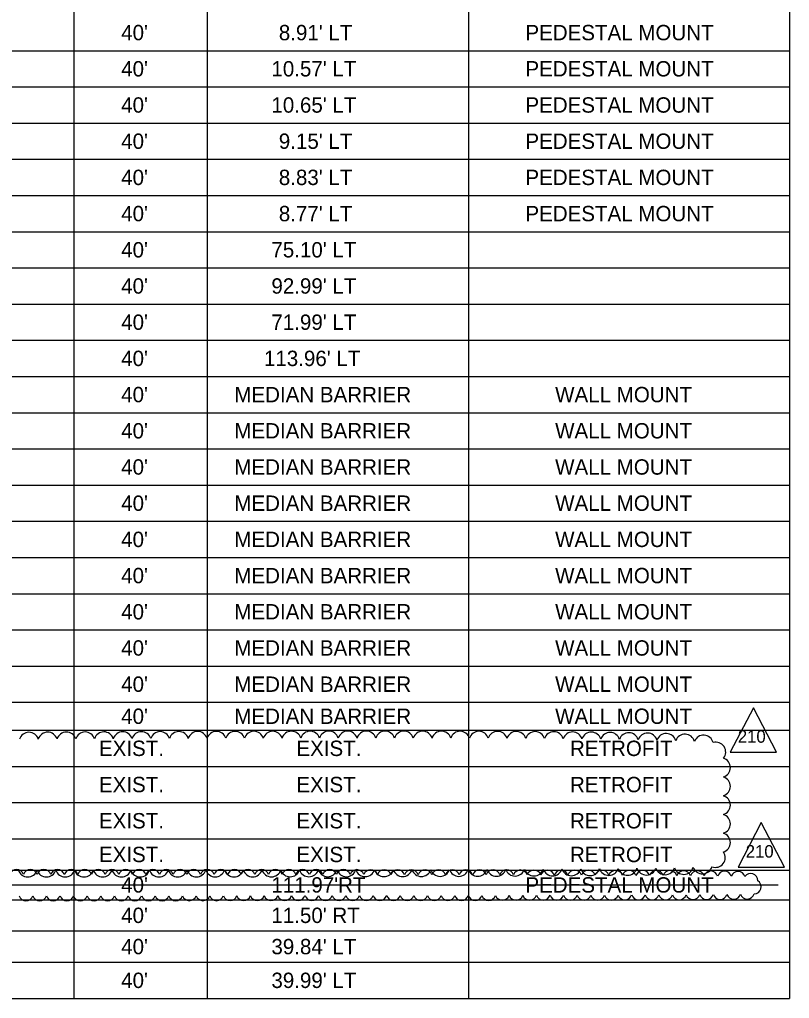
# Model space of a CAD drawing. Extents: x -818.1 to -802.4, y -2221.2 to -2187.7.
# Drawn here: x -813.196 to -809.686, y -2206.269 to -2201.807 of the extents above; entities that cross this region are included whole.
import ezdxf

# ---------------------------------------------------------------- set-up
doc = ezdxf.new("R2010")
doc.units = 0
for name, color, linetype in [('Cloud_dp', 7, 'Continuous'), ('SumBoxBorder_dp', 7, 'Continuous'), ('SumBoxLines_dp', 7, 'Continuous'), ('SumBoxLinesMin_dp', 7, 'Continuous'), ('TextLabel', 7, 'Continuous')]:
    doc.layers.add(name, color=color, linetype=linetype)

msp = doc.modelspace()

# ---------------------------------------------------------------- linework, layer by layer
at = {"layer": 'Cloud_dp'}
msp.add_line((-817.0974, -2205.7517), (-809.7376, -2205.7517), dxfattribs=at)
for points in [[(-809.85, -2204.9439), (-809.9557, -2205.1473), (-809.7444, -2205.1473)], [(-809.8139, -2205.4676), (-809.9195, -2205.6711), (-809.7083, -2205.6711)]]:
    msp.add_lwpolyline(points, close=True, dxfattribs=at)
for centre, radius, start, end in [((-812.2982, -2205.0969), 0.0448, 17.6898, 162.6898), ((-812.2127, -2205.0966), 0.0448, 17.6723, 162.6723), ((-812.1272, -2205.0964), 0.0448, 17.6538, 162.6538), ((-812.0418, -2205.0962), 0.0448, 17.6341, 162.6341), ((-811.9563, -2205.096), 0.0448, 17.6131, 162.6131), ((-811.8708, -2205.0959), 0.0448, 17.5908, 162.5908), ((-811.7854, -2205.0957), 0.0448, 17.5668, 162.5668), ((-811.6999, -2205.0957), 0.0448, 17.5411, 162.5411), ((-811.6144, -2205.0956), 0.0448, 17.5134, 162.5134), ((-811.529, -2205.0956), 0.0448, 17.4834, 162.4834), ((-811.4435, -2205.0957), 0.0448, 17.4509, 162.4509), ((-811.358, -2205.0958), 0.0448, 17.4153, 162.4153), ((-811.2726, -2205.0959), 0.0448, 17.3762, 162.3762), ((-811.1871, -2205.0961), 0.0448, 17.333, 162.333), ((-811.1016, -2205.0964), 0.0448, 17.285, 162.285), ((-811.0162, -2205.0968), 0.0448, 17.231, 162.231), ((-813.1529, -2205.1008), 0.0448, 17.8129, 162.8129), ((-813.0674, -2205.1003), 0.0448, 17.8098, 162.8098), ((-812.982, -2205.0999), 0.0448, 17.8016, 162.8016), ((-812.8965, -2205.0995), 0.0448, 17.7899, 162.7899), ((-812.811, -2205.099), 0.0448, 17.7775, 162.7775), ((-812.7255, -2205.0986), 0.0448, 17.7646, 162.7646), ((-812.6401, -2205.0982), 0.0448, 17.7511, 162.7511), ((-812.5546, -2205.0979), 0.0448, 17.737, 162.737), ((-812.4691, -2205.0975), 0.0448, 17.7221, 162.7221), ((-812.3837, -2205.0972), 0.0448, 17.7064, 162.7064), ((-810.9307, -2205.0972), 0.0448, 17.1699, 162.1699), ((-810.8452, -2205.0978), 0.0448, 17.0999, 162.0999), ((-810.7598, -2205.0984), 0.0448, 17.0185, 162.0185), ((-810.6743, -2205.0992), 0.0448, 16.9224, 161.9224), ((-810.5889, -2205.1002), 0.0448, 16.8064, 161.8064), ((-810.5035, -2205.1013), 0.0448, 16.6627, 161.6627), ((-810.418, -2205.1027), 0.0448, 16.4778, 161.4778), ((-810.3326, -2205.1044), 0.0448, 16.2276, 161.2276), ((-810.2473, -2205.1066), 0.0448, 15.861, 160.861), ((-810.162, -2205.1095), 0.0448, 15.2441, 160.2441), ((-810.077, -2205.1139), 0.0448, 13.804, 158.804), ((-810.021, -2205.1462), 0.0448, 321.1304, 106.1304), ((-809.9996, -2205.2171), 0.0448, 287.5, 72.5), ((-809.9996, -2205.3025), 0.0448, 287.5, 72.5), ((-809.9996, -2205.388), 0.0448, 287.5, 72.5), ((-809.9996, -2205.4735), 0.0448, 287.5, 72.5), ((-809.9996, -2205.559), 0.0448, 287.5, 72.5), ((-810.0231, -2205.627), 0.0448, 249.3736, 34.3736), ((-810.5091, -2205.6637), 0.0448, 198.0389, 343.0389), ((-810.4236, -2205.6629), 0.0448, 198.1252, 343.1252), ((-810.3382, -2205.6618), 0.0448, 198.2415, 343.2415), ((-810.2527, -2205.6606), 0.0448, 198.4108, 343.4108), ((-810.1673, -2205.659), 0.0448, 198.6925, 343.6925), ((-810.082, -2205.6568), 0.0448, 199.3286, 344.3286), ((-813.2089, -2205.7137), 0.0325, 17.4918, 162.4918), ((-813.1586, -2205.6707), 0.0448, 197.4879, 342.4879), ((-813.1468, -2205.7137), 0.0325, 17.4899, 162.4899), ((-813.0732, -2205.6707), 0.0448, 197.496, 342.496), ((-813.0848, -2205.7137), 0.0325, 17.4881, 162.4881), ((-813.0227, -2205.7137), 0.0325, 17.4861, 162.4861), ((-812.9877, -2205.6707), 0.0448, 197.5026, 342.5026), ((-812.9607, -2205.7137), 0.0325, 17.4841, 162.4841), ((-812.9022, -2205.6707), 0.0448, 197.5082, 342.5082), ((-812.8986, -2205.7138), 0.0325, 17.4821, 162.4821), ((-812.8366, -2205.7138), 0.0325, 17.48, 162.48), ((-812.8168, -2205.6707), 0.0448, 197.514, 342.514), ((-812.7745, -2205.7138), 0.0325, 17.4778, 162.4778), ((-812.7313, -2205.6706), 0.0448, 197.5201, 342.5201), ((-812.7124, -2205.7138), 0.0325, 17.4755, 162.4755), ((-812.6458, -2205.6706), 0.0448, 197.5265, 342.5265), ((-812.6504, -2205.7138), 0.0325, 17.4732, 162.4732), ((-812.5883, -2205.7139), 0.0325, 17.4708, 162.4708), ((-812.5603, -2205.6705), 0.0448, 197.5333, 342.5333), ((-812.5263, -2205.7139), 0.0325, 17.4683, 162.4683), ((-812.4749, -2205.6705), 0.0448, 197.5403, 342.5403), ((-812.4642, -2205.7139), 0.0325, 17.4657, 162.4657), ((-812.4021, -2205.714), 0.0325, 17.463, 162.463), ((-812.3894, -2205.6704), 0.0448, 197.5477, 342.5477), ((-812.3401, -2205.714), 0.0325, 17.4602, 162.4602), ((-812.3039, -2205.6704), 0.0448, 197.5556, 342.5556), ((-812.278, -2205.7141), 0.0325, 17.4573, 162.4573), ((-812.2184, -2205.6703), 0.0448, 197.5639, 342.5639), ((-812.216, -2205.7141), 0.0325, 17.4543, 162.4543), ((-812.1539, -2205.7142), 0.0325, 17.4512, 162.4512), ((-812.133, -2205.6702), 0.0448, 197.5726, 342.5726), ((-812.0919, -2205.7142), 0.0325, 17.448, 162.448), ((-812.0475, -2205.67), 0.0448, 197.5819, 342.5819), ((-812.0298, -2205.7143), 0.0325, 17.4446, 162.4446), ((-811.962, -2205.6699), 0.0448, 197.5918, 342.5918), ((-811.9677, -2205.7143), 0.0325, 17.4411, 162.4411), ((-811.9057, -2205.7144), 0.0325, 17.4374, 162.4374), ((-811.8765, -2205.6698), 0.0448, 197.6024, 342.6024), ((-811.8436, -2205.7145), 0.0325, 17.4335, 162.4335), ((-811.7911, -2205.6696), 0.0448, 197.6137, 342.6137), ((-811.7816, -2205.7146), 0.0325, 17.4294, 162.4294), ((-811.7195, -2205.7146), 0.0325, 17.4252, 162.4252), ((-811.7056, -2205.6694), 0.0448, 197.6259, 342.6259), ((-811.6575, -2205.7147), 0.0325, 17.4207, 162.4207), ((-811.6201, -2205.6692), 0.0448, 197.639, 342.639), ((-811.5954, -2205.7148), 0.0325, 17.416, 162.416), ((-811.5347, -2205.669), 0.0448, 197.6531, 342.6531), ((-811.5333, -2205.7149), 0.0325, 17.411, 162.411), ((-811.4713, -2205.715), 0.0325, 17.4057, 162.4057), ((-811.4492, -2205.6688), 0.0448, 197.6685, 342.6685), ((-811.4092, -2205.7151), 0.0325, 17.4002, 162.4002), ((-811.3637, -2205.6685), 0.0448, 197.6853, 342.6853), ((-811.3472, -2205.7152), 0.0325, 17.3942, 162.3942), ((-811.2782, -2205.6682), 0.0448, 197.7038, 342.7038), ((-811.2851, -2205.7153), 0.0325, 17.3879, 162.3879), ((-811.223, -2205.7155), 0.0325, 17.3812, 162.3812), ((-811.1928, -2205.6679), 0.0448, 197.7241, 342.7241), ((-811.161, -2205.7156), 0.0325, 17.374, 162.374), ((-811.1073, -2205.6676), 0.0448, 197.7468, 342.7468), ((-811.0989, -2205.7157), 0.0325, 17.3662, 162.3662), ((-811.0369, -2205.7159), 0.0325, 17.3579, 162.3579), ((-811.0218, -2205.6672), 0.0448, 197.7722, 342.7722), ((-810.9748, -2205.716), 0.0325, 17.3488, 162.3488), ((-810.9364, -2205.6667), 0.0448, 197.801, 342.801), ((-810.9128, -2205.7162), 0.0325, 17.339, 162.339), ((-810.8509, -2205.6663), 0.0448, 197.8339, 342.8339), ((-810.8507, -2205.7164), 0.0325, 17.3282, 162.3282), ((-810.7887, -2205.7166), 0.0325, 17.3164, 162.3164), ((-810.7654, -2205.6657), 0.0448, 197.8722, 342.8722), ((-810.7266, -2205.7168), 0.0325, 17.3033, 162.3033), ((-810.68, -2205.6651), 0.0448, 197.9173, 342.9173), ((-810.6645, -2205.717), 0.0325, 17.2888, 162.2888), ((-810.5945, -2205.6645), 0.0448, 197.9717, 342.9717), ((-810.6025, -2205.7172), 0.0325, 17.2724, 162.2724), ((-810.5404, -2205.7175), 0.0325, 17.2538, 162.2538), ((-810.4784, -2205.7178), 0.0325, 17.2324, 162.2324), ((-810.4163, -2205.7181), 0.0325, 17.2076, 162.2076), ((-810.3543, -2205.7184), 0.0325, 17.1781, 162.1781), ((-810.2922, -2205.7188), 0.0325, 17.1424, 162.1424), ((-810.2302, -2205.7192), 0.0325, 17.098, 162.098), ((-810.1681, -2205.7197), 0.0325, 17.0404, 162.0404), ((-810.1061, -2205.7202), 0.0325, 16.9617, 161.9617), ((-810.044, -2205.7208), 0.0325, 16.8443, 161.8443), ((-809.982, -2205.7217), 0.0325, 16.6401, 161.6401), ((-809.9201, -2205.7229), 0.0325, 16.1079, 161.1079), ((-809.8623, -2205.7327), 0.0325, 359.6037, 144.6037), ((-809.8475, -2205.7602), 0.0325, 271.8825, 56.8825), ((-813.1665, -2205.7914), 0.0325, 197.5069, 342.5069), ((-813.1045, -2205.7914), 0.0325, 197.5084, 342.5084), ((-813.0424, -2205.7914), 0.0325, 197.51, 342.51), ((-812.9803, -2205.7913), 0.0325, 197.5116, 342.5116), ((-812.9183, -2205.7913), 0.0325, 197.5133, 342.5133), ((-812.8562, -2205.7913), 0.0325, 197.515, 342.515), ((-812.7942, -2205.7913), 0.0325, 197.5168, 342.5168), ((-812.7321, -2205.7913), 0.0325, 197.5186, 342.5186), ((-812.6701, -2205.7913), 0.0325, 197.5205, 342.5205), ((-812.608, -2205.7912), 0.0325, 197.5224, 342.5224), ((-812.5459, -2205.7912), 0.0325, 197.5245, 342.5245), ((-812.4839, -2205.7912), 0.0325, 197.5265, 342.5265), ((-812.4218, -2205.7911), 0.0325, 197.5287, 342.5287), ((-812.3598, -2205.7911), 0.0325, 197.531, 342.531), ((-812.2977, -2205.7911), 0.0325, 197.5333, 342.5333), ((-812.2356, -2205.791), 0.0325, 197.5357, 342.5357), ((-812.1736, -2205.791), 0.0325, 197.5382, 342.5382), ((-812.1115, -2205.791), 0.0325, 197.5408, 342.5408), ((-812.0495, -2205.7909), 0.0325, 197.5435, 342.5435), ((-811.9874, -2205.7909), 0.0325, 197.5464, 342.5464), ((-811.9254, -2205.7908), 0.0325, 197.5493, 342.5493), ((-811.8633, -2205.7908), 0.0325, 197.5524, 342.5524), ((-811.8012, -2205.7907), 0.0325, 197.5557, 342.5557), ((-811.7392, -2205.7906), 0.0325, 197.5591, 342.5591), ((-811.6771, -2205.7906), 0.0325, 197.5627, 342.5627), ((-811.6151, -2205.7905), 0.0325, 197.5664, 342.5664), ((-811.553, -2205.7904), 0.0325, 197.5704, 342.5704), ((-811.491, -2205.7903), 0.0325, 197.5745, 342.5745), ((-811.4289, -2205.7903), 0.0325, 197.579, 342.579), ((-811.3668, -2205.7902), 0.0325, 197.5836, 342.5836), ((-811.3048, -2205.7901), 0.0325, 197.5886, 342.5886), ((-811.2427, -2205.79), 0.0325, 197.5939, 342.5939), ((-811.1807, -2205.7899), 0.0325, 197.5996, 342.5996), ((-811.1186, -2205.7898), 0.0325, 197.6056, 342.6056), ((-811.0565, -2205.7897), 0.0325, 197.6121, 342.6121), ((-810.9945, -2205.7895), 0.0325, 197.6192, 342.6192), ((-810.9324, -2205.7894), 0.0325, 197.6268, 342.6268), ((-810.8704, -2205.7893), 0.0325, 197.6351, 342.6351), ((-810.8083, -2205.7891), 0.0325, 197.6441, 342.6441), ((-810.7463, -2205.7889), 0.0325, 197.6541, 342.6541), ((-810.6842, -2205.7888), 0.0325, 197.6651, 342.6651), ((-810.6222, -2205.7886), 0.0325, 197.6774, 342.6774), ((-810.5601, -2205.7884), 0.0325, 197.6912, 342.6912), ((-810.498, -2205.7882), 0.0325, 197.7069, 342.7069), ((-810.436, -2205.7879), 0.0325, 197.725, 342.725), ((-810.3739, -2205.7877), 0.0325, 197.7461, 342.7461), ((-810.3119, -2205.7874), 0.0325, 197.7711, 342.7711), ((-810.2498, -2205.7871), 0.0325, 197.8015, 342.8015), ((-810.1878, -2205.7867), 0.0325, 197.8394, 342.8394), ((-810.1257, -2205.7863), 0.0325, 197.8888, 342.8888), ((-810.0637, -2205.7859), 0.0325, 197.9568, 342.9568), ((-810.0016, -2205.7853), 0.0325, 198.0592, 343.0592), ((-809.9396, -2205.7846), 0.0325, 198.2413, 343.2413), ((-809.8777, -2205.7836), 0.0325, 198.7573, 343.7573)]:
    msp.add_arc(centre, radius, start, end, dxfattribs=at)
at = {"layer": 'SumBoxBorder_dp'}
for p, q in [((-809.6857, -2199.4742), (-809.6857, -2206.2692)), ((-817.2082, -2206.2692), (-811.1482, -2206.2692)), ((-811.1482, -2206.2692), (-809.6857, -2206.2692))]:
    msp.add_line(p, q, dxfattribs=at)
at = {"layer": 'SumBoxLines_dp'}
for p, q in [((-812.9482, -2199.8042), (-812.9482, -2206.2692)), ((-812.9482, -2199.8042), (-812.9482, -2206.2692)), ((-812.3407, -2199.8042), (-812.3407, -2206.2692)), ((-812.3407, -2199.8042), (-812.3407, -2206.2692)), ((-811.1482, -2199.8042), (-811.1482, -2206.2692)), ((-811.1482, -2199.8042), (-811.1482, -2206.2692))]:
    msp.add_line(p, q, dxfattribs=at)
at = {"layer": 'SumBoxLinesMin_dp'}
for p, q in [((-817.2082, -2201.9492), (-809.6857, -2201.9492)), ((-817.2082, -2201.9492), (-809.6857, -2201.9492)), ((-817.2082, -2202.1142), (-809.6857, -2202.1142)), ((-817.2082, -2202.1142), (-809.6857, -2202.1142)), ((-817.2082, -2202.2792), (-809.6857, -2202.2792)), ((-817.2082, -2202.2792), (-809.6857, -2202.2792)), ((-817.2082, -2202.4442), (-809.6857, -2202.4442)), ((-817.2082, -2202.4442), (-809.6857, -2202.4442)), ((-817.2082, -2202.6092), (-809.6857, -2202.6092)), ((-817.2082, -2202.6092), (-809.6857, -2202.6092)), ((-817.2082, -2202.7742), (-809.6857, -2202.7742)), ((-817.2082, -2202.7742), (-809.6857, -2202.7742)), ((-817.2082, -2202.9392), (-809.6857, -2202.9392)), ((-817.2082, -2202.9392), (-809.6857, -2202.9392)), ((-817.2082, -2203.1042), (-809.6857, -2203.1042)), ((-817.2082, -2203.1042), (-809.6857, -2203.1042)), ((-817.2082, -2203.2692), (-809.6857, -2203.2692)), ((-817.2082, -2203.2692), (-809.6857, -2203.2692)), ((-817.2082, -2203.4342), (-809.6857, -2203.4342)), ((-817.2082, -2203.4342), (-809.6857, -2203.4342)), ((-817.2082, -2203.5992), (-809.6857, -2203.5992)), ((-817.2082, -2203.5992), (-809.6857, -2203.5992)), ((-817.2082, -2203.7642), (-809.6857, -2203.7642)), ((-817.2082, -2203.7642), (-809.6857, -2203.7642)), ((-817.2082, -2203.9292), (-809.6857, -2203.9292)), ((-817.2082, -2203.9292), (-809.6857, -2203.9292)), ((-817.2082, -2204.0942), (-809.6857, -2204.0942)), ((-817.2082, -2204.0942), (-809.6857, -2204.0942)), ((-817.2082, -2204.2592), (-809.6857, -2204.2592)), ((-817.2082, -2204.2592), (-809.6857, -2204.2592)), ((-817.2082, -2204.4242), (-809.6857, -2204.4242)), ((-817.2082, -2204.4242), (-809.6857, -2204.4242)), ((-817.2082, -2204.5892), (-809.6857, -2204.5892)), ((-817.2082, -2204.5892), (-809.6857, -2204.5892)), ((-817.2082, -2204.7542), (-809.6857, -2204.7542)), ((-817.2082, -2204.7542), (-809.6857, -2204.7542)), ((-817.2082, -2204.9192), (-809.6857, -2204.9192)), ((-816.2257, -2204.9192), (-809.6857, -2204.9192)), ((-817.2082, -2205.0467), (-809.6857, -2205.0467)), ((-817.2082, -2205.0467), (-809.6857, -2205.0467)), ((-817.2082, -2205.2117), (-809.6857, -2205.2117)), ((-814.2457, -2205.2117), (-809.6857, -2205.2117)), ((-817.2082, -2205.3767), (-809.6857, -2205.3767)), ((-812.9482, -2205.3767), (-809.6857, -2205.3767)), ((-817.2082, -2205.5417), (-809.6857, -2205.5417)), ((-814.2457, -2205.5417), (-809.6857, -2205.5417)), ((-817.2082, -2205.6842), (-809.6857, -2205.6842)), ((-812.9482, -2205.6842), (-809.6857, -2205.6842)), ((-817.2082, -2205.8192), (-809.6857, -2205.8192)), ((-816.7882, -2205.8192), (-811.1482, -2205.8192)), ((-817.2082, -2205.9617), (-809.6857, -2205.9617)), ((-817.2082, -2206.1042), (-809.6857, -2206.1042)), ((-813.6457, -2206.1042), (-811.1482, -2206.1042))]:
    msp.add_line(p, q, dxfattribs=at)

# ---------------------------------------------------------------- texts
at = {"layer": 'Cloud_dp'}
for p in [(-809.921, -2205.1037), (-809.8849, -2205.6274)]:
    msp.add_text('210', height=0.057, dxfattribs=at).set_placement(p)
at = {"layer": 'TextLabel'}
for s, p in [("40'", (-812.7324, -2201.9017)), ("8.91' LT", (-812.0137, -2201.9017)), ('PEDESTAL MOUNT', (-810.8894, -2201.9017)), ("40'", (-812.7324, -2202.0667)), ("10.57' LT", (-812.0475, -2202.0667)), ('PEDESTAL MOUNT', (-810.8894, -2202.0667)), ("40'", (-812.7324, -2202.2317)), ("10.65' LT", (-812.0475, -2202.2317)), ('PEDESTAL MOUNT', (-810.8894, -2202.2317)), ("40'", (-812.7324, -2202.3967)), ("9.15' LT", (-812.0137, -2202.3967)), ('PEDESTAL MOUNT', (-810.8894, -2202.3967)), ("40'", (-812.7324, -2202.5617)), ("8.83' LT", (-812.0137, -2202.5617)), ('PEDESTAL MOUNT', (-810.8894, -2202.5617)), ("40'", (-812.7324, -2202.7267)), ("8.77' LT", (-812.0137, -2202.7267)), ('PEDESTAL MOUNT', (-810.8894, -2202.7267)), ("40'", (-812.7324, -2202.8917)), ("75.10' LT", (-812.0475, -2202.8917)), ("40'", (-812.7324, -2203.0567)), ("92.99' LT", (-812.0475, -2203.0567)), ("40'", (-812.7324, -2203.2217)), ("71.99' LT", (-812.0475, -2203.2217)), ("40'", (-812.7324, -2203.3867)), ("113.96' LT", (-812.0814, -2203.3867)), ("40'", (-812.7324, -2203.5517)), ('MEDIAN BARRIER', (-812.2165, -2203.5517)), ('WALL MOUNT', (-810.7539, -2203.5517)), ("40'", (-812.7324, -2203.7167)), ('MEDIAN BARRIER', (-812.2165, -2203.7167)), ('WALL MOUNT', (-810.7539, -2203.7167)), ("40'", (-812.7324, -2203.8817)), ('MEDIAN BARRIER', (-812.2165, -2203.8817)), ('WALL MOUNT', (-810.7539, -2203.8817)), ("40'", (-812.7324, -2204.0467)), ('MEDIAN BARRIER', (-812.2165, -2204.0467)), ('WALL MOUNT', (-810.7539, -2204.0467)), ("40'", (-812.7324, -2204.2117)), ('MEDIAN BARRIER', (-812.2165, -2204.2117)), ('WALL MOUNT', (-810.7539, -2204.2117)), ("40'", (-812.7324, -2204.3767)), ('MEDIAN BARRIER', (-812.2165, -2204.3767)), ('WALL MOUNT', (-810.7539, -2204.3767)), ("40'", (-812.7324, -2204.5417)), ('MEDIAN BARRIER', (-812.2165, -2204.5417)), ('WALL MOUNT', (-810.7539, -2204.5417)), ("40'", (-812.7324, -2204.7067)), ('MEDIAN BARRIER', (-812.2165, -2204.7067)), ('WALL MOUNT', (-810.7539, -2204.7067)), ("40'", (-812.7324, -2204.8717)), ('MEDIAN BARRIER', (-812.2165, -2204.8717)), ('WALL MOUNT', (-810.7539, -2204.8717)), ("40'", (-812.7324, -2205.0179)), ('MEDIAN BARRIER', (-812.2165, -2205.0179)), ('WALL MOUNT', (-810.7539, -2205.0179)), ('EXIST.', (-812.8337, -2205.1642)), ('EXIST.', (-811.9337, -2205.1642)), ('RETROFIT', (-810.6862, -2205.1642)), ('EXIST.', (-812.8337, -2205.3292)), ('EXIST.', (-811.9337, -2205.3292)), ('RETROFIT', (-810.6862, -2205.3292)), ('EXIST.', (-812.8337, -2205.4942)), ('EXIST.', (-811.9337, -2205.4942)), ('RETROFIT', (-810.6862, -2205.4942)), ('EXIST.', (-812.8337, -2205.6479)), ('EXIST.', (-811.9337, -2205.6479)), ('RETROFIT', (-810.6862, -2205.6479)), ("40'", (-812.7324, -2205.7867)), ("111.97'RT", (-812.0475, -2205.7867)), ('PEDESTAL MOUNT', (-810.8894, -2205.7867)), ("40'", (-812.7324, -2205.9254)), ("11.50' RT", (-812.0475, -2205.9254)), ("40'", (-812.7324, -2206.0679)), ("39.84' LT", (-812.0475, -2206.0679)), ("40'", (-812.7324, -2206.2217)), ("39.99' LT", (-812.0475, -2206.2217))]:
    msp.add_text(s, height=0.07, dxfattribs=at).set_placement(p)

doc.saveas('drawing.dxf')
